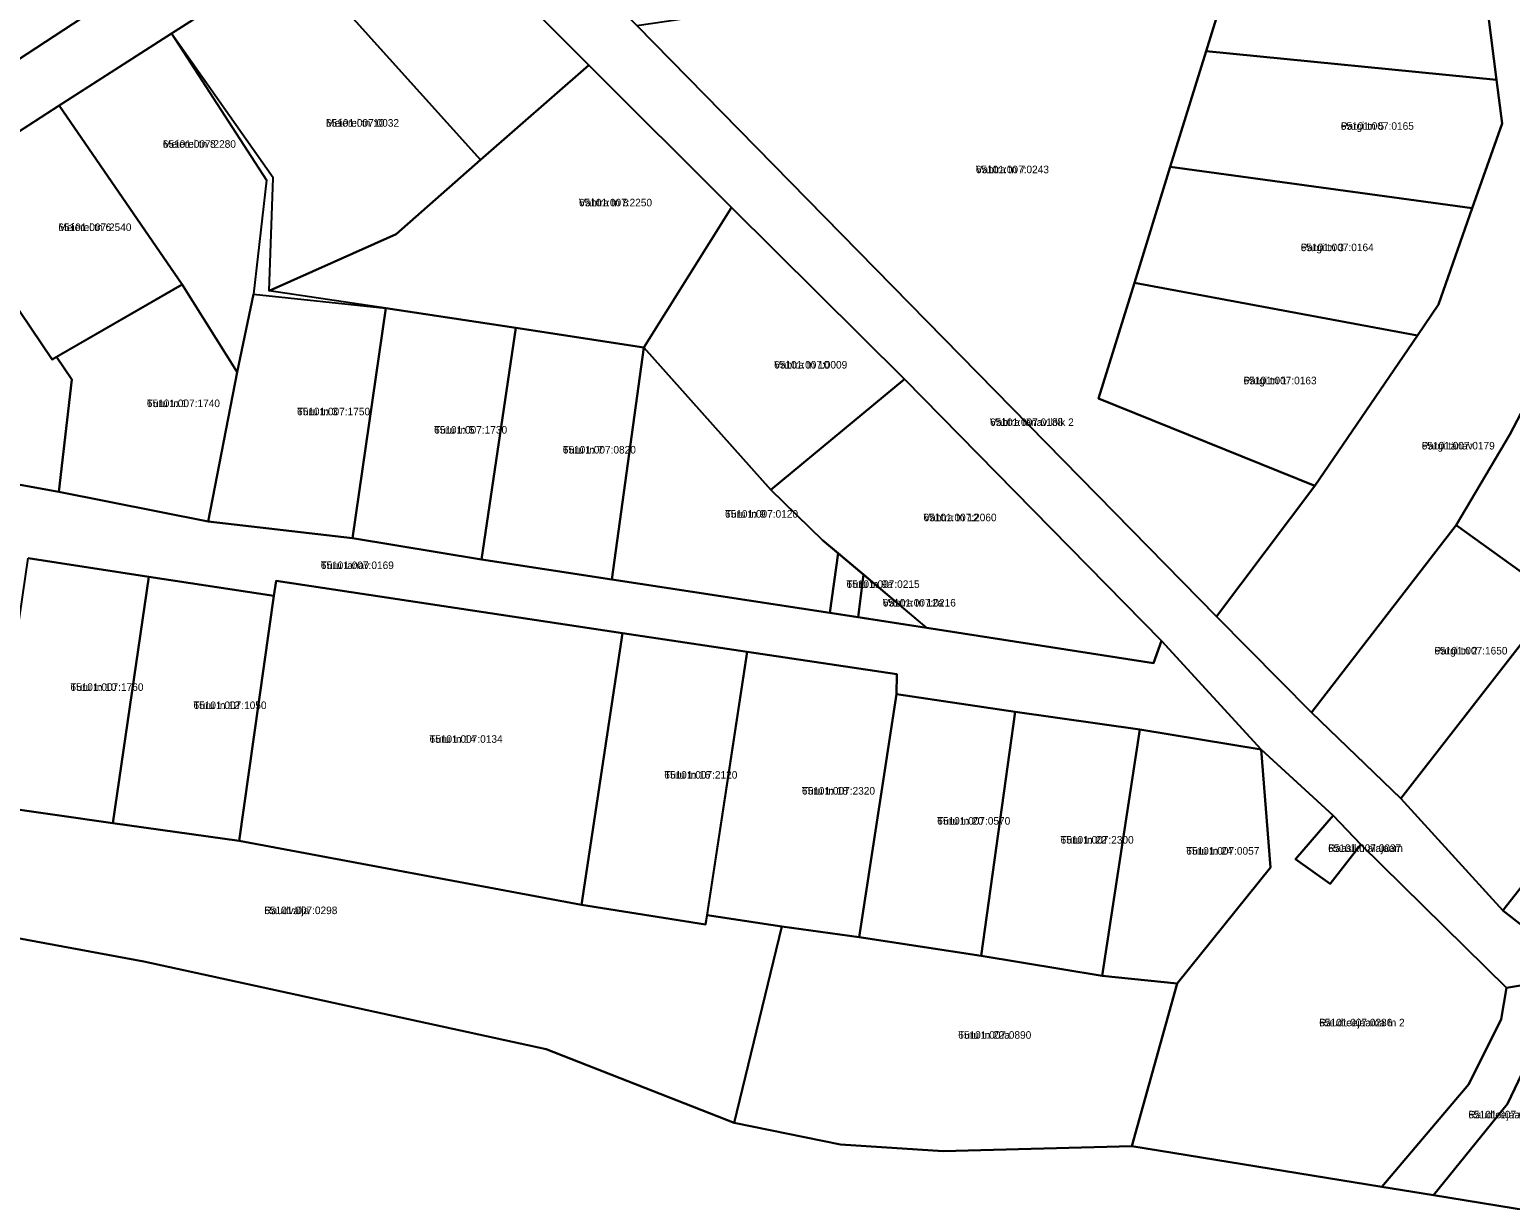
# Model space of a CAD drawing. Extents: x 556044 to 574504, y 6567077 to 6586269.
# Drawn here: x 567080 to 567373.8, y 6581396.3 to 6581628.6 of the extents above; entities that cross this region are included whole.
import ezdxf

# ---------------------------------------------------------------- set-up
doc = ezdxf.new("R2010")
doc.units = 0
for name, color, linetype in [('L_AADRESS', 7, 'Continuous'), ('PIIR', 7, 'Continuous'), ('TUNNUS', 7, 'Continuous')]:
    doc.layers.add(name, color=color, linetype=linetype)

msp = doc.modelspace()

# ---------------------------------------------------------------- linework, layer by layer
at = {"layer": 'PIIR'}
for points in [[(566867.31, 6581506.14), (566883.3, 6581503.67), (566902.2, 6581507.27), (566919.12, 6581517.92), (566918.6, 6581518.7), (566970.04, 6581553.01), (566974.46, 6581556.22), (567013.09, 6581581), (567036.65, 6581596.08), (567056.01, 6581608.51), (567077.58, 6581622.54), (567099.59, 6581637.02), (567144.85, 6581666.66), (567157.57, 6581671.76), (567199.02, 6581683.51), (567236.08, 6581693.66), (567265.79, 6581702.12), (567297.39, 6581710.83), (567356.11, 6581726.65), (567371.73, 6581731.37), (567434.22, 6581749.07)], [(567374.48, 6581718.3), (567325.12, 6581704.5), (567306.26, 6581699.46), (567279.05, 6581691.89), (567250.44, 6581683.96), (567225.07, 6581677.21), (567168.28, 6581661.43), (567154.47, 6581658.14), (567132.73, 6581643.59), (567108.11, 6581627.8), (567085.44, 6581613.26), (567061.12, 6581597.61), (567001.81, 6581557.4), (566978.5, 6581541.73), (566954.26, 6581525.74), (566915.51, 6581499.92), (566917.8, 6581497.62), (566928.98, 6581495.85), (566926.09, 6581477.65), (566926.27, 6581467.58), (566867.87, 6581479.18)], [(567382.58, 6581440.11), (567373, 6581438.51), (567344.09, 6581466.95), (567338.61, 6581472.69), (567324.3, 6581485.79), (567304.52, 6581507.32), (567253.54, 6581559.23), (567219.22, 6581593.28), (567190.94, 6581621.55), (567154.47, 6581658.14), (567168.28, 6581661.43), (567200.45, 6581629.4), (567315.49, 6581512.18), (567334.34, 6581493.11), (567352.02, 6581476.04), (567372.26, 6581453.88), (567376.17, 6581450.8)], [(567023.8, 6581548.16), (567085.74, 6581536.88), (567115.38, 6581531.01), (567143.99, 6581527.69), (567169.65, 6581523.48), (567195.48, 6581519.49), (567238.71, 6581512.88), (567257.96, 6581509.93), (567302.98, 6581502.91), (567304.52, 6581507.32), (567324.3, 6581485.79), (567300.26, 6581489.79), (567275.53, 6581493.25), (567251.94, 6581496.76), (567252.04, 6581500.75), (567222.33, 6581505.17), (567197.6, 6581508.9), (567128.86, 6581519.27), (567128.44, 6581516.26), (567103.63, 6581520.06), (567079.67, 6581523.73)], [(566517.44, 6581496.04), (566678.33, 6581471.19), (566677.09, 6581462.48), (566705.86, 6581458.56), (566707.25, 6581465.32), (566721.03, 6581463.17), (566738.32, 6581463.38), (566789.38, 6581457.39), (566863.73, 6581450.26), (566922.58, 6581441.83), (566926.27, 6581467.58), (566926.09, 6581477.65), (566934.29, 6581474.88), (567102.63, 6581443.76), (567182.44, 6581426.31), (567219.77, 6581411.75), (567240.84, 6581407.44), (567261.22, 6581406.14), (567298.67, 6581407.13), (567348.27, 6581399.04), (567358.51, 6581397.38), (567440.79, 6581383.96)]]:
    msp.add_lwpolyline(points, dxfattribs=at)
for points in [[(567077.58, 6581622.54), (567049.44, 6581664.62), (567052.39, 6581666.53), (567070.56, 6581678.54), (567099.59, 6581637.02)], [(567462.59, 6581666.33), (567459.89, 6581627.86), (567458.07, 6581605.8), (567454.72, 6581561.56), (567453.18, 6581542.92), (567444.07, 6581529.32), (567431.19, 6581511.25), (567416.67, 6581492.08), (567403.37, 6581470.78), (567417.19, 6581460.99), (567400.31, 6581456.2), (567379.26, 6581450.38), (567376.17, 6581450.8), (567372.26, 6581453.88), (567396.83, 6581485.04), (567422.25, 6581520.25), (567441.74, 6581549.44), (567442.47, 6581559.93), (567446.17, 6581607.05), (567450.84, 6581665.17)], [(567154.47, 6581658.14), (567190.94, 6581621.55), (567169.41, 6581602.79), (567132.73, 6581643.59)], [(567315.49, 6581512.18), (567334.96, 6581538.08), (567355.32, 6581567.95), (567359.48, 6581574.07), (567366.19, 6581593.15), (567372.11, 6581609.97), (567371.02, 6581618.65), (567366.61, 6581653.63), (567391.21, 6581657.13), (567396.85, 6581609.93), (567392.35, 6581593.39), (567383.79, 6581567.57), (567373.67, 6581548.26), (567363.02, 6581530.31), (567334.34, 6581493.11)], [(567320.47, 6581647.26), (567339.55, 6581649.81), (567366.61, 6581653.63), (567371.02, 6581618.65), (567313.38, 6581624.3)], [(567200.45, 6581629.4), (567236.66, 6581634.77), (567262.82, 6581638.62), (567292.28, 6581643.06), (567320.47, 6581647.26), (567313.38, 6581624.3), (567306.28, 6581601.35), (567299.18, 6581578.4), (567292.07, 6581555.45), (567334.96, 6581538.08), (567315.49, 6581512.18)], [(567132.73, 6581643.59), (567169.41, 6581602.79), (567152.7, 6581587.99), (567127.51, 6581576.8), (567128.27, 6581599.18), (567108.11, 6581627.8)], [(567108.11, 6581627.8), (567126.97, 6581598.75), (567124.38, 6581576.14), (567121.13, 6581560.64), (567110.21, 6581578.07), (567085.82, 6581613.53)], [(567313.38, 6581624.3), (567371.02, 6581618.65), (567372.11, 6581609.97), (567366.19, 6581593.15), (567306.28, 6581601.35)], [(567201.84, 6581565.52), (567176.44, 6581569.43), (567150.64, 6581573.32), (567127.51, 6581576.8), (567152.7, 6581587.99), (567169.41, 6581602.79), (567190.94, 6581621.55), (567219.22, 6581593.28)], [(567061.12, 6581597.61), (567085.82, 6581613.53), (567110.21, 6581578.07), (567084.41, 6581563.14)], [(567306.28, 6581601.35), (567366.19, 6581593.15), (567359.48, 6581574.07), (567355.32, 6581567.95), (567299.18, 6581578.4)], [(567001.81, 6581557.4), (567061.12, 6581597.61), (567084.41, 6581563.14), (567085.31, 6581563.66), (567088.3, 6581559.18), (567085.74, 6581536.88), (567023.8, 6581548.16), (567009.02, 6581551.49)], [(567219.22, 6581593.28), (567253.54, 6581559.23), (567227.04, 6581537.31), (567201.84, 6581565.52)], [(567085.74, 6581536.88), (567088.3, 6581559.18), (567085.31, 6581563.66), (567110.21, 6581578.07), (567121.13, 6581560.64), (567115.38, 6581531.01)], [(567299.18, 6581578.4), (567355.32, 6581567.95), (567334.96, 6581538.08), (567292.07, 6581555.45)], [(567143.99, 6581527.69), (567115.38, 6581531.01), (567121.13, 6581560.64), (567124.38, 6581576.14), (567150.64, 6581573.32)], [(567143.99, 6581527.69), (567150.64, 6581573.32), (567176.44, 6581569.43), (567169.65, 6581523.48)], [(567176.44, 6581569.43), (567201.84, 6581565.52), (567195.47, 6581519.49), (567169.65, 6581523.48)], [(567397.3, 6581536.76), (567383.03, 6581515.86), (567363.02, 6581530.31), (567373.67, 6581548.26), (567383.79, 6581567.57), (567411.69, 6581560.8), (567410.81, 6581557.57)], [(567195.48, 6581519.49), (567201.84, 6581565.52), (567227.04, 6581537.31), (567237.28, 6581527.33), (567240.38, 6581524.72), (567238.71, 6581512.88)], [(567302.98, 6581502.91), (567257.96, 6581509.93), (567237.28, 6581527.33), (567227.04, 6581537.31), (567253.54, 6581559.23), (567304.52, 6581507.32)], [(567375.26, 6581505.86), (567352.02, 6581476.04), (567334.34, 6581493.11), (567363.02, 6581530.31), (567383.03, 6581515.86), (567375.98, 6581506.8)], [(567240.38, 6581524.72), (567245.4, 6581520.49), (567244.38, 6581512.02), (567238.71, 6581512.88)], [(567079.67, 6581523.73), (567103.63, 6581520.06), (567096.5, 6581471.16), (567072.47, 6581474.64)], [(567103.63, 6581520.06), (567128.44, 6581516.26), (567121.56, 6581467.68), (567096.5, 6581471.16)], [(567128.86, 6581519.27), (567197.6, 6581508.9), (567189.45, 6581454.96), (567121.56, 6581467.68), (567128.44, 6581516.26)], [(567245.4, 6581520.49), (567257.94, 6581509.95), (567244.38, 6581512.02)], [(567222.33, 6581505.17), (567214.09, 6581451.09), (567189.45, 6581454.96), (567197.6, 6581508.9)], [(567214.37, 6581452.92), (567222.33, 6581505.17), (567252.04, 6581500.75), (567251.94, 6581496.76), (567244.54, 6581448.54), (567229.22, 6581450.68)], [(567352.02, 6581476.04), (567375.98, 6581506.8), (567396.83, 6581485.04), (567372.26, 6581453.88)], [(567275.53, 6581493.25), (567268.79, 6581444.87), (567244.54, 6581448.54), (567251.94, 6581496.76)], [(566937.4, 6581494.51), (566980.4, 6581487.7), (567000.22, 6581485.19), (567024.98, 6581481.53), (567048.72, 6581478.09), (567072.47, 6581474.64), (567096.5, 6581471.16), (567121.56, 6581467.68), (567189.45, 6581454.96), (567214.09, 6581451.09), (567214.37, 6581452.92), (567229.22, 6581450.68), (567219.77, 6581411.75), (567182.44, 6581426.31), (567102.63, 6581443.76), (566934.29, 6581474.88)], [(567275.53, 6581493.25), (567300.26, 6581489.79), (567292.77, 6581440.87), (567268.79, 6581444.87)], [(567324.3, 6581485.79), (567326.16, 6581462.39), (567307.65, 6581439.35), (567292.77, 6581440.87), (567300.26, 6581489.79)], [(567324.3, 6581485.79), (567338.61, 6581472.69), (567331.12, 6581464.04), (567338.03, 6581459.11), (567344.09, 6581466.95), (567373, 6581438.51), (567371.93, 6581432.32), (567365.5, 6581419.37), (567348.27, 6581399.04), (567298.67, 6581407.13), (567307.65, 6581439.35), (567326.16, 6581462.39)], [(567344.09, 6581466.95), (567338.03, 6581459.11), (567331.12, 6581464.04), (567338.61, 6581472.69)], [(567240.84, 6581407.44), (567219.77, 6581411.75), (567229.22, 6581450.68), (567244.54, 6581448.54), (567268.79, 6581444.87), (567292.77, 6581440.87), (567307.65, 6581439.35), (567298.67, 6581407.13), (567261.22, 6581406.14)], [(567382.58, 6581440.11), (567379.62, 6581428.94), (567373.17, 6581415.53), (567358.51, 6581397.38), (567348.27, 6581399.04), (567365.5, 6581419.37), (567371.93, 6581432.32), (567373, 6581438.51)], [(567382.58, 6581440.11), (567440.79, 6581383.96), (567358.51, 6581397.38), (567373.17, 6581415.53), (567379.62, 6581428.94)]]:
    msp.add_lwpolyline(points, close=True, dxfattribs=at)

# ---------------------------------------------------------------- texts
at = {"layer": 'L_AADRESS'}
for s, p in [('Meierei tn 10', (567138.76, 6581609.34)), ('Pargi tn 5', (567340.12, 6581608.73)), ('Meierei tn 8', (567106.39, 6581605.16)), ('Vahtra tn 7', (567267.71, 6581600.11)), ('Vahtra tn 8', (567188.96, 6581593.54)), ('Meierei tn 6', (567085.66, 6581588.65)), ('Pargi tn 3', (567332.16, 6581584.65)), ('Vahtra tn 10', (567227.69, 6581561.36)), ('Pargi tn 1', (567320.82, 6581558.24)), ('Turu tn 1', (567103.22, 6581553.72)), ('Turu tn 3', (567133.01, 6581552.09)), ('Vahtra tänav lõik 2', (567270.52, 6581549.97)), ('Turu tn 5', (567160.21, 6581548.45)), ('Turu tn 7', (567185.75, 6581544.5)), ('Pargi tänav', (567356.17, 6581545.31)), ('Turu tn 9', (567217.93, 6581531.78)), ('Vahtra tn 12', (567257.32, 6581531.07)), ('Turu tänav', (567137.73, 6581521.59)), ('Turu tn 9a', (567242.05, 6581517.84)), ('Vahtra tn 12a', (567249.24, 6581514.15)), ('Pargi tn 2', (567358.69, 6581504.64)), ('Turu tn 10', (567088.05, 6581497.42)), ('Turu tn 12', (567112.47, 6581493.82)), ('Turu tn 14', (567159.31, 6581487.12)), ('Turu tn 16', (567205.89, 6581480.01)), ('Turu tn 18', (567233.2, 6581476.84)), ('Turu tn 20', (567260.04, 6581470.88)), ('Turu tn 22', (567284.52, 6581467.12)), ('Turu tn 24', (567309.46, 6581464.93)), ('Raasiku alajaam', (567337.61, 6581465.47)), ('Raudvälja', (567126.52, 6581453.13)), ('Raudteejaama tn 2', (567335.84, 6581430.87)), ('Turu tn 22a', (567264.21, 6581428.41)), ('Raudteejaama tänav', (567365.43, 6581412.61))]:
    msp.add_text(s, height=1.5, dxfattribs=at).set_placement(p)
at = {"layer": 'TUNNUS'}
for s, p in [('65101:007:0032', (567138.76, 6581609.34)), ('65101:007:0165', (567340.12, 6581608.73)), ('65101:007:2280', (567106.39, 6581605.16)), ('65101:007:0243', (567267.71, 6581600.11)), ('65101:007:2250', (567188.96, 6581593.54)), ('65101:007:2540', (567085.66, 6581588.65)), ('65101:007:0164', (567332.16, 6581584.65)), ('65101:007:0009', (567227.69, 6581561.36)), ('65101:007:0163', (567320.82, 6581558.24)), ('65101:007:1740', (567103.22, 6581553.72)), ('65101:007:1750', (567133.01, 6581552.09)), ('65101:007:0188', (567270.52, 6581549.97)), ('65101:007:1730', (567160.21, 6581548.45)), ('65101:007:0820', (567185.75, 6581544.5)), ('65101:007:0179', (567356.17, 6581545.31)), ('65101:007:0120', (567217.93, 6581531.78)), ('65101:007:2060', (567257.32, 6581531.07)), ('65101:007:0169', (567137.73, 6581521.59)), ('65101:007:0215', (567242.05, 6581517.84)), ('65101:007:0216', (567249.24, 6581514.15)), ('65101:007:1650', (567358.69, 6581504.64)), ('65101:007:1760', (567088.05, 6581497.42)), ('65101:007:1050', (567112.47, 6581493.82)), ('65101:007:0134', (567159.31, 6581487.12)), ('65101:007:2120', (567205.89, 6581480.01)), ('65101:007:2320', (567233.2, 6581476.84)), ('65101:007:0570', (567260.04, 6581470.88)), ('65101:007:2300', (567284.52, 6581467.12)), ('65101:007:0057', (567309.46, 6581464.93)), ('65101:007:0037', (567337.61, 6581465.47)), ('65101:007:0298', (567126.52, 6581453.13)), ('65101:007:0286', (567335.84, 6581430.87)), ('65101:007:0890', (567264.21, 6581428.41)), ('65101:007:0178', (567365.43, 6581412.61))]:
    msp.add_text(s, height=1.5, dxfattribs=at).set_placement(p)

doc.saveas('drawing.dxf')
